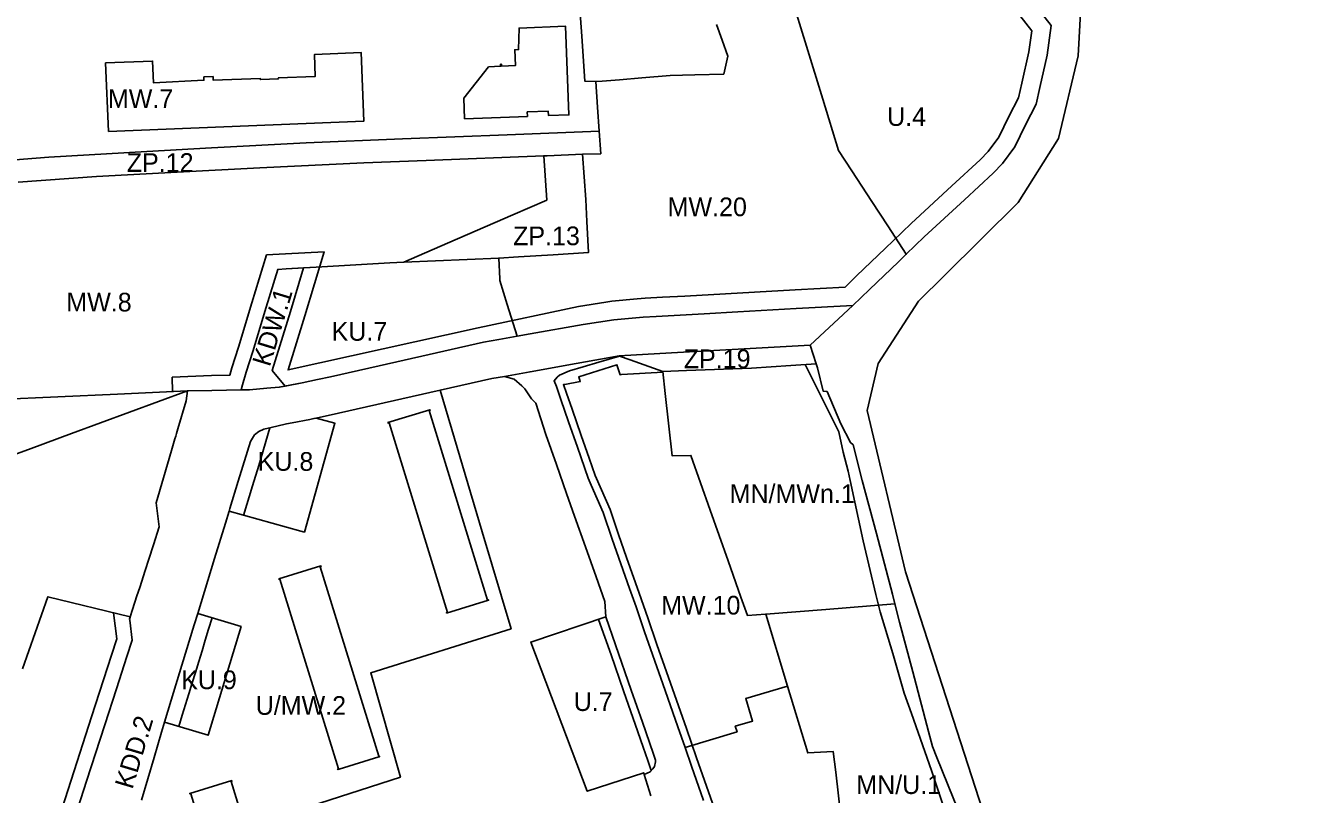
# Model space of a CAD drawing. Extents: x 7429178 to 7430831, y 5550228 to 5551611.
# Drawn here: x 7430171.5 to 7430511.7, y 5551009.6 to 5551215.2 of the extents above; entities that cross this region are included whole.
import ezdxf

# ---------------------------------------------------------------- set-up
doc = ezdxf.new("R2010")
doc.units = 0
for name, color, linetype in [('linie rozgraniczające', 7, 'Continuous'), ('nieprzekraczalne linie zabudowy', 7, 'Continuous'), ('obowiazujace linie zabudowy', 7, 'Continuous'), ('przeznaczenia terenów', 7, 'Continuous')]:
    doc.layers.add(name, color=color, linetype=linetype)

msp = doc.modelspace()

# ---------------------------------------------------------------- linework, layer by layer
at = {"layer": 'linie rozgraniczające'}
for points in [[(7430411.61, 5551158.64), (7430406.82, 5551154.03), (7430401.87, 5551161.62), (7430397.6, 5551168.16), (7430392.26, 5551176.35), (7430388.73, 5551181.76), (7430384.53, 5551195.49), (7430380.2, 5551209.64), (7430376.02, 5551223.29), (7430378.33, 5551237.93), (7430388.84, 5551236.12), (7430414.19, 5551231.47), (7430434.2, 5551228.01), (7430436.29, 5551227.12), (7430445.59, 5551215.17), (7430444.52, 5551207.22), (7430442.56, 5551198.65), (7430441.54, 5551194.19), (7430438.73, 5551188.59), (7430435.8, 5551182.74), (7430432.52, 5551178.26), (7430430.09, 5551175.69), (7430422.42, 5551168.61)], [(7430297.92, 5551152.99), (7430272.61, 5551151.91), (7430282.15, 5551156.06), (7430301.66, 5551164.54), (7430310.78, 5551168.51), (7430309.97, 5551180.34), (7430309.97, 5551180.34), (7430310.88, 5551180.38), (7430320.27, 5551180.76), (7430321.16, 5551168.69), (7430321.5, 5551162.79), (7430321.96, 5551154.51), (7430312.46, 5551153.91), (7430303.23, 5551153.33)], [(7430231.25, 5551117.77), (7430229.07, 5551117.73), (7430229.47, 5551119.12), (7430230.48, 5551122.5), (7430232.19, 5551128.02), (7430235.82, 5551139.89), (7430238.9, 5551149.99), (7430241.14, 5551150.12), (7430245.78, 5551150.38), (7430242.25, 5551138.72), (7430237.41, 5551122.94), (7430240.87, 5551118.77), (7430239.28, 5551118.46), (7430235.95, 5551118.18), (7430231.3, 5551117.8), (7430231.28, 5551117.79)], [(7430240.87, 5551118.77), (7430237.41, 5551122.94), (7430242.25, 5551138.72), (7430245.78, 5551150.38), (7430249.18, 5551150.58), (7430268.85, 5551151.7), (7430272.61, 5551151.91), (7430297.92, 5551152.99), (7430298.21, 5551147.47), (7430298.23, 5551147), (7430300.19, 5551140.63), (7430302.82, 5551132.14), (7430297.97, 5551131.27), (7430293.9, 5551130.55), (7430293.89, 5551130.53), (7430270.68, 5551125.28), (7430252.96, 5551121.28), (7430249.54, 5551120.55), (7430245.42, 5551119.66)], [(7430348.08, 5551122.92), (7430341.77, 5551122.7), (7430333.07, 5551125.79), (7430330.19, 5551126.81), (7430330.13, 5551126.85), (7430337.88, 5551127.28), (7430345.74, 5551127.72), (7430365.09, 5551128.8), (7430381.11, 5551129.69), (7430382.76, 5551124.72), (7430375.97, 5551124.26), (7430365.45, 5551123.53)], [(7430341.77, 5551122.7), (7430342.43, 5551116.78), (7430344.26, 5551100.16), (7430349.3, 5551100.24), (7430354.47, 5551085.6), (7430359.23, 5551072.05), (7430362.64, 5551062.35), (7430364.44, 5551057.42), (7430369.2, 5551057.75), (7430369.27, 5551057.75), (7430375.05, 5551038.57), (7430375.05, 5551038.57), (7430363.92, 5551035.21), (7430365.77, 5551029.19), (7430361.15, 5551027.81), (7430361.63, 5551026.34), (7430347.73, 5551022.1), (7430347.73, 5551022.1), (7430345.79, 5551027.63), (7430341.75, 5551039.19), (7430336.89, 5551053.09), (7430334.61, 5551059.71), (7430332.85, 5551064.69), (7430328.27, 5551077.84), (7430325.8, 5551085.01), (7430322.62, 5551092.32), (7430321.8, 5551094.16), (7430318.98, 5551102.4), (7430316.6, 5551109.2), (7430314.55, 5551115.2), (7430313.33, 5551118.67), (7430312.72, 5551120.15), (7430313.52, 5551121.12), (7430314.19, 5551121.69), (7430316.81, 5551122.82), (7430320.48, 5551123.9), (7430324.67, 5551125.13), (7430330.19, 5551126.81), (7430333.07, 5551125.79)], [(7430392.6, 5551103.1), (7430395.02, 5551093.51), (7430398.89, 5551079.34), (7430403.11, 5551063.16), (7430403.79, 5551060.54), (7430403.77, 5551060.54), (7430385.34, 5551059.07), (7430369.27, 5551057.75), (7430369.2, 5551057.75), (7430364.44, 5551057.42), (7430362.64, 5551062.35), (7430359.23, 5551072.05), (7430354.47, 5551085.6), (7430349.3, 5551100.24), (7430344.26, 5551100.16), (7430342.43, 5551116.78), (7430341.77, 5551122.7), (7430348.08, 5551122.92), (7430365.45, 5551123.53), (7430375.97, 5551124.26), (7430382.76, 5551124.72), (7430383.13, 5551123.63), (7430384.66, 5551117.39), (7430385.67, 5551117.3), (7430389.3, 5551108.72), (7430391.93, 5551103.65)], [(7430231.59, 5551103.97), (7430232.65, 5551105.72), (7430233.8, 5551106.6), (7430235.19, 5551107.24), (7430237.13, 5551107.71), (7430240.86, 5551108.58), (7430241.23, 5551108.66), (7430242.7, 5551108.94), (7430247.43, 5551109.87), (7430248.18, 5551110.03), (7430248.5, 5551110.09), (7430248.65, 5551110.13), (7430249.12, 5551110.23), (7430254.15, 5551108.82), (7430246.02, 5551079.72), (7430245.08, 5551079.98), (7430225.88, 5551085.34), (7430226.1, 5551086.06), (7430228.33, 5551093.31), (7430230.79, 5551101.37)], [(7430413.85, 5551022.39), (7430415.02, 5551019.47), (7430419.34, 5551008.71), (7430421.11, 5551004.3), (7430421.92, 5551002.28), (7430425.22, 5550991.24), (7430427.64, 5550983.15), (7430419.02, 5550981.87), (7430412.4, 5550981.17), (7430402.69, 5550980.57), (7430392.11, 5550979.97), (7430390.79, 5550991.31), (7430389.44, 5551002.92), (7430387.97, 5551015.55), (7430387.33, 5551021.05), (7430380.51, 5551020.7), (7430375.05, 5551038.57), (7430369.27, 5551057.75), (7430385.34, 5551059.07), (7430403.77, 5551060.54), (7430403.79, 5551060.54), (7430405.06, 5551055.65), (7430408.57, 5551042.36), (7430412.78, 5551026.44)], [(7430208.63, 5551028.95), (7430210.43, 5551034.8), (7430213.29, 5551044.18), (7430216.58, 5551054.91), (7430217.51, 5551057.98), (7430229.08, 5551054.48), (7430220.33, 5551025.42), (7430208.64, 5551028.95)], [(7430338.36, 5551015.66), (7430336.83, 5551014.89), (7430336.67, 5551015.41), (7430321.57, 5551010.45), (7430306.48, 5551050.35), (7430326.51, 5551057.06), (7430329.13, 5551049.55), (7430333.35, 5551037.45), (7430336.32, 5551028.95), (7430339.22, 5551020.62), (7430339.86, 5551018.79), (7430339.79, 5551018.28), (7430339.53, 5551017.07), (7430339.12, 5551016.4)]]:
    msp.add_lwpolyline(points, close=True, dxfattribs=at)
for points in [[(7430453.92, 5551228.43), (7430452.8, 5551207.06), (7430447.48, 5551184.97), (7430436.75, 5551167.9), (7430417.03, 5551148.36), (7430410.12, 5551141.52), (7430399.35, 5551124.8), (7430396.42, 5551112.21), (7430406.64, 5551069.14), (7430427.25, 5551005.18), (7430445.89, 5550940.42), (7430457.32, 5550900.71), (7430473.38, 5550844.91), (7430478.4, 5550824.47), (7430511.65, 5550687.91)], [(7430419.34, 5551008.71), (7430415.02, 5551019.47), (7430413.85, 5551022.39), (7430412.78, 5551026.44), (7430408.57, 5551042.36), (7430405.06, 5551055.65), (7430403.79, 5551060.54), (7430403.11, 5551063.16), (7430398.89, 5551079.34), (7430395.02, 5551093.51), (7430392.6, 5551103.1), (7430391.93, 5551103.65), (7430389.3, 5551108.72), (7430385.67, 5551117.3), (7430384.66, 5551117.39), (7430383.13, 5551123.63), (7430382.76, 5551124.72), (7430381.11, 5551129.69), (7430392.59, 5551140.35), (7430397.02, 5551144.61), (7430404.75, 5551152.04), (7430406.82, 5551154.03), (7430411.61, 5551158.64), (7430422.42, 5551168.61), (7430430.09, 5551175.69), (7430432.52, 5551178.26), (7430435.8, 5551182.74), (7430438.73, 5551188.59), (7430441.54, 5551194.19), (7430442.56, 5551198.65), (7430444.52, 5551207.22), (7430445.59, 5551215.17), (7430436.29, 5551227.12)], [(7430376.02, 5551223.29), (7430380.2, 5551209.64), (7430384.53, 5551195.49), (7430388.73, 5551181.76), (7430392.26, 5551176.35), (7430397.6, 5551168.16), (7430401.87, 5551161.62), (7430406.82, 5551154.03), (7430404.75, 5551152.04), (7430397.02, 5551144.61), (7430392.59, 5551140.35), (7430377.44, 5551139.5), (7430361.85, 5551138.63), (7430352.84, 5551138.13), (7430339.96, 5551137.41), (7430336.5, 5551137.19), (7430328.72, 5551136.49), (7430320.46, 5551135.21), (7430306.37, 5551132.77), (7430302.82, 5551132.14), (7430300.19, 5551140.63), (7430298.23, 5551147), (7430298.21, 5551147.47), (7430297.92, 5551152.99), (7430303.23, 5551153.33), (7430312.46, 5551153.91), (7430321.96, 5551154.51), (7430321.5, 5551162.79), (7430321.16, 5551168.69), (7430320.27, 5551180.76), (7430325.19, 5551180.91), (7430324.78, 5551186.9), (7430324.33, 5551193.38), (7430323.86, 5551200.17), (7430325.56, 5551200.29), (7430330.24, 5551200.67), (7430336.13, 5551201.19), (7430343.78, 5551201.86), (7430350.33, 5551202.02), (7430358.06, 5551202.2), (7430359.16, 5551207.01), (7430357.63, 5551211.22), (7430356.08, 5551215.49)], [(7430319.52, 5551220.76), (7430320.11, 5551212.36), (7430320.95, 5551200.3), (7430323.86, 5551200.17), (7430324.33, 5551193.38), (7430324.78, 5551186.9), (7430324.78, 5551186.9), (7430300.21, 5551185.95), (7430272.18, 5551184.84), (7430246.48, 5551183.8), (7430221.22, 5551182.46), (7430203.86, 5551181.53), (7430177.75, 5551180), (7430149.51, 5551177.75)], [(7430356.08, 5551215.49), (7430357.63, 5551211.22), (7430359.16, 5551207.01), (7430358.06, 5551202.2), (7430350.33, 5551202.02), (7430343.78, 5551201.86), (7430336.13, 5551201.19), (7430330.24, 5551200.67), (7430325.56, 5551200.29), (7430323.86, 5551200.17), (7430320.95, 5551200.3), (7430320.11, 5551212.36), (7430319.52, 5551220.76)], [(7430149.51, 5551177.75), (7430177.75, 5551180), (7430203.86, 5551181.53), (7430221.22, 5551182.46), (7430246.48, 5551183.8), (7430272.18, 5551184.84), (7430300.21, 5551185.95), (7430324.78, 5551186.9), (7430324.78, 5551186.9), (7430325.19, 5551180.91), (7430320.27, 5551180.76), (7430310.88, 5551180.38), (7430309.97, 5551180.34), (7430278.55, 5551179.08), (7430261.91, 5551178.44), (7430234.09, 5551177.13), (7430212.03, 5551175.96), (7430190.47, 5551174.81), (7430169.48, 5551173.32)], [(7430169.48, 5551173.32), (7430190.47, 5551174.81), (7430212.03, 5551175.96), (7430234.09, 5551177.13), (7430261.91, 5551178.44), (7430278.55, 5551179.08), (7430309.97, 5551180.34), (7430310.78, 5551168.51), (7430301.66, 5551164.54), (7430282.15, 5551156.06), (7430272.61, 5551151.91), (7430268.85, 5551151.7), (7430249.18, 5551150.58), (7430241.14, 5551150.12), (7430238.9, 5551149.99), (7430235.82, 5551139.89), (7430232.19, 5551128.02), (7430230.48, 5551122.5), (7430229.47, 5551119.12), (7430229.07, 5551117.73), (7430221.27, 5551117.6), (7430214.79, 5551117.49), (7430196.03, 5551116.65), (7430164.1, 5551115.22)], [(7430183.84, 5551000.93), (7430187.78, 5551013.14), (7430192.64, 5551028.18), (7430195.75, 5551037.8), (7430198.56, 5551046.5), (7430199.96, 5551050.84), (7430199.31, 5551056.2), (7430199.26, 5551056.46), (7430199.35, 5551056.75), (7430199.42, 5551056.95), (7430199.45, 5551057.06), (7430200.08, 5551059.01), (7430201.26, 5551062.66), (7430202.01, 5551064.96), (7430203.46, 5551069.46), (7430204.45, 5551072.52), (7430205.68, 5551076.35), (7430207.22, 5551081.11), (7430206.35, 5551087.58), (7430208.32, 5551094.22), (7430210.49, 5551101.57), (7430211.42, 5551104.68), (7430211.62, 5551105.38), (7430211.82, 5551106.06), (7430212.18, 5551107.36), (7430212.21, 5551107.36), (7430214.42, 5551114.82), (7430214.79, 5551117.49), (7430221.27, 5551117.6), (7430229.07, 5551117.73), (7430231.25, 5551117.77), (7430231.28, 5551117.79), (7430231.3, 5551117.8), (7430235.95, 5551118.18), (7430239.28, 5551118.46), (7430245.42, 5551119.66), (7430249.54, 5551120.55), (7430252.96, 5551121.28), (7430270.68, 5551125.28), (7430293.89, 5551130.53), (7430293.9, 5551130.55), (7430297.97, 5551131.27), (7430302.82, 5551132.14), (7430306.37, 5551132.77), (7430320.46, 5551135.21), (7430328.72, 5551136.49), (7430336.5, 5551137.19), (7430339.96, 5551137.41), (7430352.84, 5551138.13), (7430361.85, 5551138.63), (7430377.44, 5551139.5), (7430392.59, 5551140.35), (7430381.11, 5551129.69), (7430365.09, 5551128.8), (7430345.74, 5551127.72), (7430337.88, 5551127.28), (7430330.13, 5551126.85), (7430318.59, 5551124.79), (7430306.3, 5551122.6), (7430299.49, 5551121.38), (7430296.1, 5551120.78), (7430282.29, 5551117.66), (7430255.11, 5551111.51), (7430249.12, 5551110.23), (7430248.65, 5551110.13), (7430248.5, 5551110.09), (7430248.18, 5551110.03), (7430247.43, 5551109.87), (7430242.7, 5551108.94), (7430241.23, 5551108.66), (7430240.86, 5551108.58), (7430237.13, 5551107.71), (7430235.19, 5551107.24), (7430233.8, 5551106.6), (7430232.65, 5551105.72), (7430231.59, 5551103.97), (7430230.79, 5551101.37), (7430228.33, 5551093.31), (7430226.1, 5551086.06), (7430225.88, 5551085.34), (7430224.89, 5551082.08), (7430222, 5551072.69), (7430217.51, 5551057.98), (7430216.58, 5551054.91), (7430213.29, 5551044.18), (7430210.43, 5551034.8), (7430208.63, 5551028.95), (7430207.8, 5551026.24), (7430205.83, 5551019.51), (7430202.46, 5551008.03)], [(7430338.57, 5551009.2), (7430336.83, 5551014.89), (7430338.36, 5551015.66), (7430339.12, 5551016.4), (7430339.53, 5551017.07), (7430339.79, 5551018.28), (7430339.86, 5551018.79), (7430339.22, 5551020.62), (7430336.32, 5551028.95), (7430333.35, 5551037.45), (7430329.13, 5551049.55), (7430326.51, 5551057.06), (7430326.25, 5551061.18), (7430323.93, 5551067.78), (7430321.12, 5551075.76), (7430318.22, 5551083.98), (7430316.08, 5551090.05), (7430313.35, 5551097.8), (7430310.51, 5551105.84), (7430307.88, 5551114.2), (7430306.66, 5551115.38), (7430304.93, 5551118.05), (7430304.06, 5551118.82), (7430302.03, 5551120.61), (7430299.49, 5551121.38), (7430306.3, 5551122.6), (7430318.59, 5551124.79), (7430330.13, 5551126.85), (7430330.19, 5551126.81), (7430324.67, 5551125.13), (7430320.48, 5551123.9), (7430316.81, 5551122.82), (7430314.19, 5551121.69), (7430313.52, 5551121.12), (7430312.72, 5551120.15), (7430313.33, 5551118.67), (7430314.55, 5551115.2), (7430316.6, 5551109.2), (7430318.98, 5551102.4), (7430321.8, 5551094.16), (7430322.62, 5551092.32), (7430325.8, 5551085.01), (7430328.27, 5551077.84), (7430332.85, 5551064.69), (7430334.61, 5551059.71), (7430336.89, 5551053.09), (7430341.75, 5551039.19), (7430345.79, 5551027.63), (7430347.73, 5551022.1), (7430349.47, 5551017.13), (7430352.68, 5551007.97)], [(7430233.79, 5551002.02), (7430271.64, 5551014.25), (7430263.73, 5551042.1), (7430301.23, 5551053.89), (7430293.54, 5551079.78), (7430282.29, 5551117.66), (7430296.1, 5551120.78), (7430299.49, 5551121.38), (7430302.03, 5551120.61), (7430304.06, 5551118.82), (7430304.93, 5551118.05), (7430306.66, 5551115.38), (7430307.88, 5551114.2), (7430310.51, 5551105.84), (7430313.35, 5551097.8), (7430316.08, 5551090.05), (7430318.22, 5551083.98), (7430321.12, 5551075.76), (7430323.93, 5551067.78), (7430326.25, 5551061.18), (7430326.51, 5551057.06), (7430306.48, 5551050.35), (7430321.57, 5551010.45), (7430336.67, 5551015.41), (7430336.83, 5551014.89), (7430338.57, 5551009.2)], [(7430146.79, 5551092.52), (7430172.97, 5551102.13), (7430183.75, 5551106.09), (7430214.79, 5551117.49), (7430214.42, 5551114.82), (7430212.21, 5551107.36), (7430212.18, 5551107.36), (7430211.82, 5551106.06), (7430211.62, 5551105.38), (7430211.42, 5551104.68), (7430210.49, 5551101.57), (7430208.32, 5551094.22), (7430206.35, 5551087.58), (7430207.22, 5551081.11), (7430205.68, 5551076.35), (7430204.45, 5551072.52), (7430203.46, 5551069.46), (7430202.01, 5551064.96), (7430201.26, 5551062.66), (7430200.08, 5551059.01), (7430199.45, 5551057.06), (7430177.48, 5551062.44), (7430170.65, 5551043.22)], [(7430164.1, 5551115.22), (7430196.03, 5551116.65), (7430214.79, 5551117.49), (7430183.75, 5551106.09), (7430172.97, 5551102.13), (7430146.79, 5551092.52)], [(7430202.46, 5551008.03), (7430205.83, 5551019.51), (7430207.8, 5551026.24), (7430208.63, 5551028.95), (7430208.64, 5551028.95), (7430220.33, 5551025.42), (7430229.08, 5551054.48), (7430217.51, 5551057.98), (7430222, 5551072.69), (7430224.89, 5551082.08), (7430225.88, 5551085.34), (7430245.08, 5551079.98), (7430246.02, 5551079.72), (7430254.15, 5551108.82), (7430249.12, 5551110.23), (7430255.11, 5551111.51), (7430282.29, 5551117.66), (7430282.29, 5551117.66), (7430293.54, 5551079.78), (7430301.23, 5551053.89), (7430263.73, 5551042.1), (7430271.64, 5551014.25), (7430233.79, 5551002.02)], [(7430170.65, 5551043.22), (7430177.48, 5551062.44), (7430199.45, 5551057.06), (7430199.45, 5551057.06), (7430199.42, 5551056.95), (7430199.42, 5551056.95), (7430199.35, 5551056.75), (7430199.26, 5551056.46), (7430199.31, 5551056.2), (7430199.96, 5551050.84), (7430199.96, 5551050.84), (7430198.56, 5551046.5), (7430195.75, 5551037.8), (7430192.64, 5551028.18), (7430187.78, 5551013.14), (7430183.84, 5551000.93), (7430181.57, 5550993.91), (7430180.06, 5550989.22), (7430177.24, 5550980.42), (7430174.04, 5550970.46), (7430170.35, 5550958.95)], [(7430352.68, 5551007.97), (7430349.47, 5551017.13), (7430347.73, 5551022.1), (7430347.73, 5551022.1), (7430361.63, 5551026.34), (7430361.15, 5551027.81), (7430365.77, 5551029.19), (7430363.92, 5551035.21), (7430375.05, 5551038.57), (7430375.05, 5551038.57), (7430380.51, 5551020.7), (7430387.33, 5551021.05), (7430387.97, 5551015.55), (7430389.44, 5551002.92)]]:
    msp.add_lwpolyline(points, dxfattribs=at)
at = {"layer": 'nieprzekraczalne linie zabudowy'}
for points in [[(7430210.79, 5551117.31), (7430210.67, 5551121.16), (7430221.15, 5551121.6), (7430226.07, 5551121.68), (7430226.65, 5551123.66), (7430228.36, 5551129.2), (7430231.99, 5551141.06), (7430235.89, 5551153.83), (7430240.91, 5551154.11), (7430251.26, 5551154.7), (7430246.08, 5551137.55), (7430241.64, 5551123.08), (7430292.43, 5551134.32), (7430319.28, 5551140.09), (7430326.56, 5551141.22), (7430328.11, 5551141.46), (7430334.93, 5551142.07), (7430337.08, 5551142.26), (7430341.68, 5551142.52), (7430347.67, 5551142.85), (7430377.16, 5551144.5), (7430390.46, 5551145.24), (7430393.56, 5551148.21), (7430401.28, 5551155.64), (7430403.36, 5551157.64), (7430408.18, 5551162.28), (7430419.03, 5551172.28), (7430426.58, 5551179.24), (7430428.67, 5551181.46), (7430431.52, 5551185.35), (7430434.26, 5551190.83), (7430436.8, 5551195.89), (7430437.69, 5551199.77), (7430439.6, 5551208.11), (7430440.35, 5551213.76), (7430435.54, 5551219.95)], [(7430341.83, 5551122.49), (7430330.74, 5551121.83), (7430330.34, 5551121.79), (7430329.52, 5551124.47), (7430319.31, 5551121.21), (7430319.69, 5551119.97), (7430315.56, 5551119.23), (7430315.23, 5551119.18), (7430316.08, 5551116.87), (7430317.56, 5551112.58), (7430320, 5551105.52), (7430322.08, 5551099.53), (7430323.66, 5551094.89), (7430325.35, 5551091.06), (7430327.67, 5551085.74), (7430329.97, 5551079.05), (7430332.08, 5551072.97), (7430335.42, 5551063.41), (7430337.73, 5551056.8), (7430340.19, 5551049.72), (7430343.29, 5551040.84), (7430348.07, 5551027.19), (7430350.8, 5551019.4), (7430356.64, 5551002.71)], [(7430417.06, 5551005.59), (7430413.54, 5551015.99), (7430408.23, 5551031.2), (7430406.31, 5551036.67), (7430403.26, 5551047.27), (7430399.89, 5551058.38), (7430398.73, 5551063.09), (7430395.34, 5551077.42), (7430391.87, 5551093.53), (7430391.34, 5551096.05), (7430390, 5551101.09), (7430388.79, 5551106.54), (7430379.83, 5551124.52)], [(7430236.72, 5551107.61), (7430233.8, 5551097.53), (7430232.15, 5551092.14), (7430229.71, 5551084.17)], [(7430162.97, 5550949.06), (7430165.63, 5550957.33), (7430169.85, 5550970.48), (7430174.4, 5550984.68), (7430178.74, 5550998.18), (7430183.66, 5551013.4), (7430189.13, 5551030.33), (7430194.45, 5551046.81), (7430195.88, 5551051.23), (7430194.95, 5551058.17)], [(7430221.34, 5551056.82), (7430220.41, 5551053.74), (7430219.52, 5551050.88), (7430218.65, 5551048.01), (7430217.77, 5551045.12), (7430216.89, 5551042.24), (7430216.02, 5551039.39), (7430215.14, 5551036.5), (7430214.25, 5551033.63), (7430213.38, 5551030.77), (7430212.47, 5551027.79)], [(7430338.67, 5551015.96), (7430337.79, 5551018.65), (7430336.54, 5551022.24), (7430335.11, 5551026.32), (7430331.29, 5551037.3), (7430327.93, 5551046.91), (7430324.61, 5551056.4)]]:
    msp.add_lwpolyline(points, dxfattribs=at)
at = {"layer": 'obowiazujace linie zabudowy'}
for points in [[(7430288.8, 5551190.24), (7430305.58, 5551190.89), (7430305.53, 5551192.07), (7430311.15, 5551192.26), (7430311.24, 5551191.11), (7430316.69, 5551191.29), (7430315.8, 5551214.97), (7430303.38, 5551214.5), (7430303.25, 5551208.75), (7430302.22, 5551208.69), (7430302.39, 5551204.45), (7430298.68, 5551204.3), (7430298.66, 5551204.84), (7430298.41, 5551204.83), (7430298.44, 5551204.27), (7430295.22, 5551204.14), (7430288.57, 5551195.78), (7430288.8, 5551190.24)], [(7430193.65, 5551186.82), (7430261.92, 5551189.62), (7430261.17, 5551207.93), (7430248.73, 5551207.44), (7430248.88, 5551201.58), (7430239.03, 5551201.17), (7430239.05, 5551200.91), (7430234.23, 5551200.73), (7430234.21, 5551201), (7430221.65, 5551200.53), (7430221.58, 5551201.54), (7430219.17, 5551201.46), (7430219.14, 5551200.54), (7430205.64, 5551199.88), (7430205.42, 5551205.68), (7430192.88, 5551205.17), (7430193.65, 5551186.82)], [(7430283.98, 5551058.05), (7430295.22, 5551061.5), (7430295.18, 5551061.65), (7430294.89, 5551061.56), (7430279.32, 5551112.24), (7430279.61, 5551112.33), (7430279.56, 5551112.47), (7430268.32, 5551109.02), (7430268.36, 5551108.88), (7430268.65, 5551108.96), (7430284.22, 5551058.28), (7430283.93, 5551058.19), (7430283.98, 5551058.05)], [(7430265.91, 5551019.61), (7430266.1, 5551019.67), (7430266.04, 5551019.86), (7430265.85, 5551019.8), (7430250.25, 5551070.46), (7430250.48, 5551070.53), (7430250.43, 5551070.68), (7430239.21, 5551067.26), (7430239.26, 5551067.08), (7430239.47, 5551067.14), (7430255.1, 5551016.48), (7430254.89, 5551016.41), (7430254.95, 5551016.22), (7430255.3, 5551016.33), (7430265.91, 5551019.61)], [(7430242.18, 5550962.25), (7430242.13, 5550962.43), (7430241.91, 5550962.36), (7430226.4, 5551013.06), (7430226.63, 5551013.13), (7430226.59, 5551013.28), (7430215.35, 5551009.86), (7430215.4, 5551009.72), (7430215.61, 5551009.75), (7430223.37, 5550984.6), (7430226.26, 5550974.88), (7430231.17, 5550959.03), (7430230.95, 5550958.96), (7430230.99, 5550958.83), (7430242.18, 5550962.25)]]:
    msp.add_lwpolyline(points, dxfattribs=at)

# ---------------------------------------------------------------- texts
at = {"layer": 'przeznaczenia terenów'}
for s, p in [('MW.7', (7430193.5, 5551193.14)), ('U.4', (7430401.71, 5551188.34)), ('ZP.12', (7430198.54, 5551176.05)), ('MW.20', (7430343.07, 5551164.2)), ('ZP.13', (7430301.78, 5551156.44)), ('MW.8', (7430182.39, 5551138.72)), ('KU.7', (7430253.27, 5551130.9)), ('ZP.19', (7430347.38, 5551123.56)), ('KU.8', (7430233.52, 5551096.12)), ('MN/MWn.1', (7430359.63, 5551087.51)), ('MW.10', (7430341.34, 5551057.69)), ('KU.9', (7430213.07, 5551037.74)), ('U/MW.2', (7430232.99, 5551030.88)), ('U.7', (7430317.97, 5551031.91)), ('MN/U.1', (7430393.49, 5551009.72))]:
    msp.add_text(s, height=5, dxfattribs=at).set_placement(p)
for s, rotation, p in [('KDW.1', 73.0422, (7430236.75, 5551123.74)), ('KDD.2', 73.3277, (7430200.04, 5551010.77))]:
    msp.add_text(s, height=5, rotation=rotation, dxfattribs=at).set_placement(p)

doc.saveas('drawing.dxf')
